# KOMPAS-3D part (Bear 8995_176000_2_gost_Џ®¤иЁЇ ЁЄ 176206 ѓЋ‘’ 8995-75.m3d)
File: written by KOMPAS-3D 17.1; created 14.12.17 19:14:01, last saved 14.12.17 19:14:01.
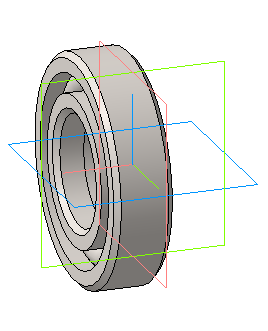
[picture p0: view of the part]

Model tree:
1. Операция без истории:1  (with: Операция без истории:2, Операция без истории:3, Операция без истории:4)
